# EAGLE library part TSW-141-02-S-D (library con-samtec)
THROUGH-HOLE .025" SQ POST HEADER Source: Samtec TSW.pdf
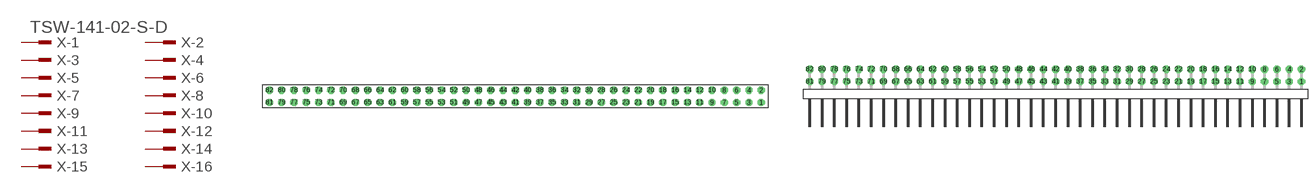
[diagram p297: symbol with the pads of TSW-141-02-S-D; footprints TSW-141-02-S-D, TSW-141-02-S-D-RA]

Designator prefix X; gates -1=MPINV -2=MPIN -3=MPIN -4=MPIN -5=MPIN -6=MPIN -7=MPIN -8=MPIN -9=MPIN -10=MPIN -11=MPIN -12=MPIN -13=MPIN -14=MPIN -15=MPIN -16=MPIN -17=MPIN -18=MPIN -19=MPIN -20=MPIN -21=MPIN -22=MPIN -23=MPIN -24=MPIN -25=MPIN -26=MPIN -27=MPIN -28=MPIN -29=MPIN -30=MPIN -31=MPIN -32=MPIN -33=MPIN -34=MPIN -35=MPIN -36=MPIN -37=MPIN -38=MPIN -39=MPIN -40=MPIN -41=MPIN -42=MPIN -43=MPIN -44=MPIN -45=MPIN -46=MPIN -47=MPIN -48=MPIN -49=MPIN -50=MPIN -51=MPIN -52=MPIN -53=MPIN -54=MPIN -55=MPIN -56=MPIN -57=MPIN -58=MPIN -59=MPIN -60=MPIN -61=MPIN -62=MPIN -63=MPIN -64=MPIN -65=MPIN -66=MPIN -67=MPIN -68=MPIN -69=MPIN -70=MPIN -71=MPIN -72=MPIN -73=MPIN -74=MPIN -75=MPIN -76=MPIN -77=MPIN -78=MPIN -79=MPIN -80=MPIN -81=MPIN -82=MPIN

## TSW-141-02-S-D (OC_FARNELL: unknown; OC_NEWARK: unknown)  [TSW-141-02-S-D]
1  -1:1  pas
2  -2:1  pas
3  -3:1  pas
4  -4:1  pas
5  -5:1  pas
6  -6:1  pas
7  -7:1  pas
8  -8:1  pas
9  -9:1  pas
10  -10:1  pas
11  -11:1  pas
12  -12:1  pas
13  -13:1  pas
14  -14:1  pas
15  -15:1  pas
16  -16:1  pas
17  -17:1  pas
18  -18:1  pas
19  -19:1  pas
20  -20:1  pas
21  -21:1  pas
22  -22:1  pas
23  -23:1  pas
24  -24:1  pas
25  -25:1  pas
26  -26:1  pas
27  -27:1  pas
28  -28:1  pas
29  -29:1  pas
30  -30:1  pas
31  -31:1  pas
32  -32:1  pas
33  -33:1  pas
34  -34:1  pas
35  -35:1  pas
36  -36:1  pas
37  -37:1  pas
38  -38:1  pas
39  -39:1  pas
40  -40:1  pas
41  -41:1  pas
42  -42:1  pas
43  -43:1  pas
44  -44:1  pas
45  -45:1  pas
46  -46:1  pas
47  -47:1  pas
48  -48:1  pas
49  -49:1  pas
50  -50:1  pas
51  -51:1  pas
52  -52:1  pas
53  -53:1  pas
54  -54:1  pas
55  -55:1  pas
56  -56:1  pas
57  -57:1  pas
58  -58:1  pas
59  -59:1  pas
60  -60:1  pas
61  -61:1  pas
62  -62:1  pas
63  -63:1  pas
64  -64:1  pas
65  -65:1  pas
66  -66:1  pas
67  -67:1  pas
68  -68:1  pas
69  -69:1  pas
70  -70:1  pas
71  -71:1  pas
72  -72:1  pas
73  -73:1  pas
74  -74:1  pas
75  -75:1  pas
76  -76:1  pas
77  -77:1  pas
78  -78:1  pas
79  -79:1  pas
80  -80:1  pas
81  -81:1  pas
82  -82:1  pas

## TSW-141-02-S-D-RA (OC_FARNELL: unknown; OC_NEWARK: unknown)  [TSW-141-02-S-D-RA]
Pads as for TSW-141-02-S-D

## Footprint TSW-141-02-S-D (pad centres in mm)
THROUGH-HOLE .025" SQ POST HEADER Source: Samtec TSW.pdf
drill 1 pad 1.5 octagon: 1 50.8,-1.27; 2 50.8,1.27; 3 48.26,-1.27; 4 48.26,1.27; 5 45.72,-1.27; 6 45.72,1.27; 7 43.18,-1.27; 8 43.18,1.27; 9 40.64,-1.27; 10 40.64,1.27; 11 38.1,-1.27; 12 38.1,1.27; 13 35.56,-1.27; 14 35.56,1.27; 15 33.02,-1.27; 16 33.02,1.27; 17 30.48,-1.27; 18 30.48,1.27; 19 27.94,-1.27; 20 27.94,1.27; 21 25.4,-1.27; 22 25.4,1.27; 23 22.86,-1.27; 24 22.86,1.27; 25 20.32,-1.27; 26 20.32,1.27; 27 17.78,-1.27; 28 17.78,1.27; 29 15.24,-1.27; 30 15.24,1.27; 31 12.7,-1.27; 32 12.7,1.27; 33 10.16,-1.27; 34 10.16,1.27; 35 7.62,-1.27; 36 7.62,1.27; 37 5.08,-1.27; 38 5.08,1.27; 39 2.54,-1.27; 40 2.54,1.27; 41 0,-1.27; 42 0,1.27; 43 -2.54,-1.27; 44 -2.54,1.27; 45 -5.08,-1.27; 46 -5.08,1.27; 47 -7.62,-1.27; 48 -7.62,1.27; 49 -10.16,-1.27; 50 -10.16,1.27; 51 -12.7,-1.27; 52 -12.7,1.27; 53 -15.24,-1.27; 54 -15.24,1.27; 55 -17.78,-1.27; 56 -17.78,1.27; 57 -20.32,-1.27; 58 -20.32,1.27; 59 -22.86,-1.27; 60 -22.86,1.27; 61 -25.4,-1.27; 62 -25.4,1.27; 63 -27.94,-1.27; 64 -27.94,1.27; 65 -30.48,-1.27; 66 -30.48,1.27; 67 -33.02,-1.27; 68 -33.02,1.27; 69 -35.56,-1.27; 70 -35.56,1.27; 71 -38.1,-1.27; 72 -38.1,1.27; 73 -40.64,-1.27; 74 -40.64,1.27; 75 -43.18,-1.27; 76 -43.18,1.27; 77 -45.72,-1.27; 78 -45.72,1.27; 79 -48.26,-1.27; 80 -48.26,1.27; 81 -50.8,-1.27; 82 -50.8,1.27

## Footprint TSW-141-02-S-D-RA (pad centres in mm)
THROUGH-HOLE .025" SQ POST HEADER Source: Samtec TSW.pdf
drill 1 pad 1.5 octagon: 1 50.8,1.524; 2 50.8,4.064; 3 48.26,1.524; 4 48.26,4.064; 5 45.72,1.524; 6 45.72,4.064; 7 43.18,1.524; 8 43.18,4.064; 9 40.64,1.524; 10 40.64,4.064; 11 38.1,1.524; 12 38.1,4.064; 13 35.56,1.524; 14 35.56,4.064; 15 33.02,1.524; 16 33.02,4.064; 17 30.48,1.524; 18 30.48,4.064; 19 27.94,1.524; 20 27.94,4.064; 21 25.4,1.524; 22 25.4,4.064; 23 22.86,1.524; 24 22.86,4.064; 25 20.32,1.524; 26 20.32,4.064; 27 17.78,1.524; 28 17.78,4.064; 29 15.24,1.524; 30 15.24,4.064; 31 12.7,1.524; 32 12.7,4.064; 33 10.16,1.524; 34 10.16,4.064; 35 7.62,1.524; 36 7.62,4.064; 37 5.08,1.524; 38 5.08,4.064; 39 2.54,1.524; 40 2.54,4.064; 41 0,1.524; 42 0,4.064; 43 -2.54,1.524; 44 -2.54,4.064; 45 -5.08,1.524; 46 -5.08,4.064; 47 -7.62,1.524; 48 -7.62,4.064; 49 -10.16,1.524; 50 -10.16,4.064; 51 -12.7,1.524; 52 -12.7,4.064; 53 -15.24,1.524; 54 -15.24,4.064; 55 -17.78,1.524; 56 -17.78,4.064; 57 -20.32,1.524; 58 -20.32,4.064; 59 -22.86,1.524; 60 -22.86,4.064; 61 -25.4,1.524; 62 -25.4,4.064; 63 -27.94,1.524; 64 -27.94,4.064; 65 -30.48,1.524; 66 -30.48,4.064; 67 -33.02,1.524; 68 -33.02,4.064; 69 -35.56,1.524; 70 -35.56,4.064; 71 -38.1,1.524; 72 -38.1,4.064; 73 -40.64,1.524; 74 -40.64,4.064; 75 -43.18,1.524; 76 -43.18,4.064; 77 -45.72,1.524; 78 -45.72,4.064; 79 -48.26,1.524; 80 -48.26,4.064; 81 -50.8,1.524; 82 -50.8,4.064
